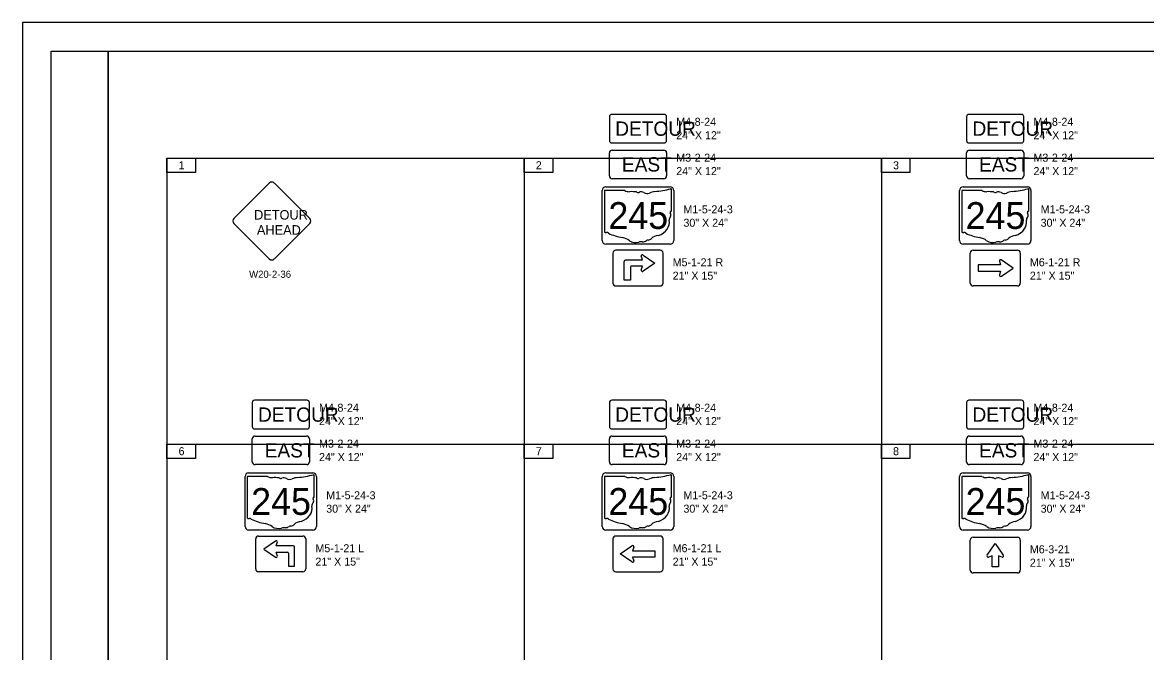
# Model space of a CAD drawing. Extents: x 0 to 718, y 0 to 440.
# Drawn here: x 0 to 393, y 220 to 440 of the extents above; entities that cross this region are included whole.
import ezdxf

# ---------------------------------------------------------------- set-up
doc = ezdxf.new("R2010")
doc.units = 0
for name, color, linetype in [('SC_Scratch1', 7, 'Continuous'), ('SH_Border', 7, 'Continuous'), ('SH_Cut_Line', 7, 'Continuous'), ('SH_Text', 7, 'Continuous'), ('SN_P_Signs', 7, 'Continuous'), ('SN_P_Text', 7, 'Continuous')]:
    doc.layers.add(name, color=color, linetype=linetype)

msp = doc.modelspace()

# ---------------------------------------------------------------- linework, layer by layer
at = {"layer": 'SC_Scratch1'}
for p, q in [((50.54, 392.53), (50.54, 292.53)), ((50.54, 392.53), (225.54, 392.53)), ((175.54, 392.53), (175.54, 292.53)), ((225.54, 392.53), (375.54, 392.53)), ((300.54, 392.53), (300.54, 292.53)), ((375.54, 392.53), (550.54, 392.53)), ((50.54, 292.53), (50.54, 192.53)), ((50.54, 292.53), (225.54, 292.53)), ((175.54, 292.53), (175.54, 192.53)), ((225.54, 292.53), (375.54, 292.53)), ((300.54, 292.53), (300.54, 192.53)), ((375.54, 292.53), (550.54, 292.53))]:
    msp.add_line(p, q, dxfattribs=at)
at = {"layer": 'SH_Border'}
for points in [[(10, 430), (30, 430), (30, 10), (10, 10)], [(30, 430), (670, 430), (670, 10), (30, 10)]]:
    msp.add_lwpolyline(points, close=True, dxfattribs=at)
at = {"layer": 'SH_Cut_Line'}
msp.add_lwpolyline([(0, 0), (680, 0), (680, 440), (0, 440)], close=True, dxfattribs=at)
at = {"layer": 'SH_Text'}
for points in [[(50.54, 392.53), (60.54, 392.53), (60.54, 387.53), (50.54, 387.53)], [(175.54, 392.53), (185.54, 392.53), (185.54, 387.53), (175.54, 387.53)], [(300.54, 392.53), (310.54, 392.53), (310.54, 387.53), (300.54, 387.53)], [(50.54, 292.53), (60.54, 292.53), (60.54, 287.53), (50.54, 287.53)], [(175.54, 292.53), (185.54, 292.53), (185.54, 287.53), (175.54, 287.53)], [(300.54, 292.53), (310.54, 292.53), (310.54, 287.53), (300.54, 287.53)]]:
    msp.add_lwpolyline(points, close=True, dxfattribs=at)
at = {"layer": 'SN_P_Signs'}
for p, q in [((205.39, 386.37), (205.39, 394.37)), ((206.39, 395.37), (224.39, 395.37)), ((225.39, 394.37), (225.39, 386.37)), ((330.39, 386.37), (330.39, 394.37)), ((331.39, 395.37), (349.39, 395.37)), ((350.39, 394.37), (350.39, 386.37)), ((224.39, 385.37), (206.39, 385.37)), ((349.39, 385.37), (331.39, 385.37)), ((210.76, 381.26), (203.9, 381.26)), ((227.11, 374.17), (227.11, 381.61)), ((335.76, 381.26), (328.9, 381.26)), ((352.11, 374.17), (352.11, 381.61)), ((203.67, 381.02), (203.67, 366.79)), ((328.67, 381.02), (328.67, 366.79)), ((227.1, 374.17), (227.11, 374.17)), ((352.1, 374.17), (352.11, 374.17)), ((206.64, 359.37), (206.64, 348.87)), ((223.14, 360.37), (207.64, 360.37)), ((216.95, 356.93), (216.53, 358.33)), ((217.24, 358.63), (221.32, 355.83)), ((224.14, 348.87), (224.14, 359.37)), ((331.64, 348.87), (331.64, 359.37)), ((332.64, 360.37), (348.14, 360.37)), ((349.14, 359.37), (349.14, 348.87)), ((210.54, 349.9), (210.54, 356.46)), ((211.01, 356.93), (216.95, 356.93)), ((211.01, 356.93), (211.01, 356.93)), ((212.73, 354.43), (212.73, 349.9)), ((216.95, 354.74), (213.04, 354.74)), ((216.53, 353.33), (216.95, 354.74)), ((221.32, 355.83), (217.24, 353.04)), ((342.26, 355.21), (334.45, 355.21)), ((334.45, 355.21), (334.45, 353.02)), ((341.86, 356.49), (342.26, 355.21)), ((346.64, 354.12), (342.5, 356.96)), ((342.56, 351.32), (346.64, 354.12)), ((212.73, 349.9), (210.54, 349.9)), ((334.45, 353.02), (342.26, 353.02)), ((342.26, 353.02), (341.86, 351.74)), ((207.64, 347.87), (223.14, 347.87)), ((348.14, 347.87), (332.64, 347.87)), ((81.39, 295.37), (99.39, 295.37)), ((206.39, 295.37), (224.39, 295.37)), ((331.39, 295.37), (349.39, 295.37)), ((80.39, 286.37), (80.39, 294.37)), ((100.39, 294.37), (100.39, 286.37)), ((205.39, 286.37), (205.39, 294.37)), ((225.39, 294.37), (225.39, 286.37)), ((330.39, 286.37), (330.39, 294.37)), ((350.39, 294.37), (350.39, 286.37)), ((99.39, 285.37), (81.39, 285.37)), ((224.39, 285.37), (206.39, 285.37)), ((349.39, 285.37), (331.39, 285.37)), ((78.67, 281.02), (78.67, 266.79)), ((85.76, 281.26), (78.9, 281.26)), ((102.11, 274.17), (102.11, 281.61)), ((203.67, 281.02), (203.67, 266.79)), ((210.76, 281.26), (203.9, 281.26)), ((227.11, 274.17), (227.11, 281.61)), ((328.67, 281.02), (328.67, 266.79)), ((335.76, 281.26), (328.9, 281.26)), ((352.11, 274.17), (352.11, 281.61)), ((102.1, 274.17), (102.11, 274.17)), ((227.1, 274.17), (227.11, 274.17)), ((352.1, 274.17), (352.11, 274.17)), ((82.64, 260.37), (98.14, 260.37)), ((223.14, 260.37), (207.64, 260.37)), ((223.14, 260.37), (223.14, 260.37)), ((332.64, 259.99), (348.14, 259.99)), ((81.64, 248.87), (81.64, 259.37)), ((88.53, 258.63), (84.45, 255.83)), ((84.45, 255.83), (88.53, 253.04)), ((88.83, 256.93), (89.24, 258.33)), ((94.76, 256.93), (88.83, 256.93)), ((94.76, 256.93), (94.76, 256.93)), ((95.23, 249.9), (95.23, 256.46)), ((99.14, 259.37), (99.14, 248.87)), ((206.64, 259.37), (206.64, 248.87)), ((209.14, 254.12), (213.28, 256.96)), ((213.91, 256.49), (213.51, 255.21)), ((224.14, 248.87), (224.14, 259.37)), ((331.64, 248.49), (331.64, 258.99)), ((337.54, 253.66), (340.39, 257.8)), ((340.39, 257.8), (343.18, 253.72)), ((349.14, 258.99), (349.14, 248.49)), ((89.24, 253.33), (88.83, 254.74)), ((88.83, 254.74), (92.73, 254.74)), ((93.04, 254.43), (93.04, 249.9)), ((213.22, 251.32), (209.14, 254.12)), ((213.51, 255.21), (221.32, 255.21)), ((221.32, 253.02), (213.51, 253.02)), ((213.51, 253.02), (213.91, 251.74)), ((221.32, 255.21), (221.32, 253.02)), ((339.29, 253.42), (338.01, 253.03)), ((339.29, 249.67), (339.29, 253.42)), ((342.76, 253.03), (341.48, 253.42)), ((341.48, 253.42), (341.48, 249.67)), ((98.14, 247.87), (82.64, 247.87)), ((93.04, 249.9), (95.23, 249.9)), ((93.04, 249.9), (95.23, 249.9)), ((207.64, 247.87), (223.14, 247.87)), ((341.48, 249.67), (339.29, 249.67)), ((348.14, 247.49), (332.64, 247.49))]:
    msp.add_line(p, q, dxfattribs=at)
for points in [[(205.39, 407.07), (205.39, 398.67)], [(224.59, 407.87), (206.19, 407.87)], [(225.39, 398.67), (225.39, 407.07)], [(330.39, 407.07), (330.39, 398.67)], [(349.59, 407.87), (331.19, 407.87)], [(350.39, 398.67), (350.39, 407.07)], [(206.19, 397.87), (224.59, 397.87)], [(331.19, 397.87), (349.59, 397.87)], [(73.99, 371.46), (86.37, 383.83)], [(88.14, 383.83), (100.51, 371.46)], [(202.89, 363.74), (202.89, 381.24)], [(204.14, 382.49), (226.64, 382.49)], [(227.89, 381.24), (227.89, 363.74)], [(327.89, 363.74), (327.89, 381.24)], [(329.14, 382.49), (351.64, 382.49)], [(352.89, 381.24), (352.89, 363.74)], [(86.37, 357.32), (73.99, 369.69)], [(100.51, 369.69), (88.14, 357.32)], [(226.64, 362.49), (204.14, 362.49)], [(351.64, 362.49), (329.14, 362.49)], [(80.39, 307.07), (80.39, 298.67)], [(99.59, 307.87), (81.19, 307.87)], [(100.39, 298.67), (100.39, 307.07)], [(205.39, 307.07), (205.39, 298.67)], [(224.59, 307.87), (206.19, 307.87)], [(225.39, 298.67), (225.39, 307.07)], [(330.39, 307.07), (330.39, 298.67)], [(349.59, 307.87), (331.19, 307.87)], [(350.39, 298.67), (350.39, 307.07)], [(81.19, 297.87), (99.59, 297.87)], [(206.19, 297.87), (224.59, 297.87)], [(331.19, 297.87), (349.59, 297.87)], [(77.89, 263.74), (77.89, 281.24)], [(79.14, 282.49), (101.64, 282.49)], [(102.89, 281.24), (102.89, 263.74)], [(202.89, 263.74), (202.89, 281.24)], [(204.14, 282.49), (226.64, 282.49)], [(227.89, 281.24), (227.89, 263.74)], [(327.89, 263.74), (327.89, 281.24)], [(329.14, 282.49), (351.64, 282.49)], [(352.89, 281.24), (352.89, 263.74)], [(101.64, 262.49), (79.14, 262.49)], [(226.64, 262.49), (204.14, 262.49)], [(351.64, 262.49), (329.14, 262.49)]]:
    msp.add_lwpolyline(points, dxfattribs=at)
for centre, radius, start, end in [((206.19, 407.07), 0.8, 90, 180), ((224.59, 407.07), 0.8, 0, 90), ((331.19, 407.07), 0.8, 90, 180), ((349.59, 407.07), 0.8, 0, 90), ((206.19, 398.67), 0.8, 180, 270), ((224.59, 398.67), 0.8, 270, 0), ((331.19, 398.67), 0.8, 180, 270), ((349.59, 398.67), 0.8, 270, 0), ((206.39, 394.36), 1, 90, 180), ((224.39, 394.36), 1, 0, 90), ((331.39, 394.36), 1, 90, 180), ((349.39, 394.36), 1, 0, 90), ((206.39, 386.36), 1, 180, 270), ((224.39, 386.36), 1, 270, 0), ((331.39, 386.36), 1, 180, 270), ((349.39, 386.36), 1, 270, 0), ((87.25, 382.95), 1.25, 45, 135), ((204.14, 381.24), 1.25, 90, 180), ((226.64, 381.24), 1.25, 0, 90), ((329.14, 381.24), 1.25, 90, 180), ((351.64, 381.24), 1.25, 0, 90), ((74.88, 370.57), 1.25, 135, 225), ((99.63, 370.57), 1.25, 315, 45), ((204.14, 363.74), 1.25, 180, 270), ((226.64, 363.74), 1.25, 270, 0), ((329.14, 363.74), 1.25, 180, 270), ((351.64, 363.74), 1.25, 270, 0), ((207.64, 359.36), 1, 90, 180), ((216.95, 358.33), 0.417, 45.0001, 179.9983), ((223.14, 359.36), 1, 0, 90), ((332.64, 359.37), 1, 90, 180), ((348.14, 359.37), 1, 0, 90), ((87.25, 358.2), 1.25, 225, 315), ((211.01, 356.46), 0.469, 90, 180), ((213.04, 354.43), 0.312, 90, 180), ((342.26, 356.62), 0.417, 55.4112, 197.2046), ((216.95, 353.33), 0.417, 179.9983, 314.9999), ((342.26, 351.62), 0.417, 162.7954, 315.0096), ((207.64, 348.86), 1, 180, 270), ((223.14, 348.86), 1, 270, 0), ((332.64, 348.87), 1, 180, 270), ((348.14, 348.87), 1, 270, 360), ((81.19, 307.07), 0.8, 90, 180), ((99.59, 307.07), 0.8, 0, 90), ((206.19, 307.07), 0.8, 90, 180), ((224.59, 307.07), 0.8, 0, 90), ((331.19, 307.07), 0.8, 90, 180), ((349.59, 307.07), 0.8, 0, 90), ((81.19, 298.67), 0.8, 180, 270), ((81.39, 294.36), 1, 90, 180), ((99.39, 294.36), 1, 0, 90), ((99.59, 298.67), 0.8, 270, 0), ((206.19, 298.67), 0.8, 180, 270), ((206.39, 294.36), 1, 90, 180), ((224.39, 294.36), 1, 0, 90), ((224.59, 298.67), 0.8, 270, 0), ((331.19, 298.67), 0.8, 180, 270), ((331.39, 294.36), 1, 90, 180), ((349.39, 294.36), 1, 0, 90), ((349.59, 298.67), 0.8, 270, 0), ((81.39, 286.36), 1, 180, 270), ((99.39, 286.36), 1, 270, 0), ((206.39, 286.36), 1, 180, 270), ((224.39, 286.36), 1, 270, 0), ((331.39, 286.36), 1, 180, 270), ((349.39, 286.36), 1, 270, 0), ((79.14, 281.24), 1.25, 90, 180), ((101.64, 281.24), 1.25, 0, 90), ((204.14, 281.24), 1.25, 90, 180), ((226.64, 281.24), 1.25, 0, 90), ((329.14, 281.24), 1.25, 90, 180), ((351.64, 281.24), 1.25, 0, 90), ((79.14, 263.74), 1.25, 180, 270), ((101.64, 263.74), 1.25, 270, 0), ((204.14, 263.74), 1.25, 180, 270), ((226.64, 263.74), 1.25, 270, 0), ((329.14, 263.74), 1.25, 180, 270), ((351.64, 263.74), 1.25, 270, 0), ((82.64, 259.37), 1, 90, 180), ((98.14, 259.37), 1, 0, 90), ((207.64, 259.37), 1, 90, 180), ((223.14, 259.37), 1, 0, 90), ((332.64, 258.99), 1, 90, 180), ((348.14, 258.99), 1, 0, 90), ((88.83, 258.33), 0.417, 0.0017, 134.9999), ((94.76, 256.46), 0.469, 0, 90), ((213.51, 256.62), 0.417, 342.7954, 124.5888), ((88.83, 253.33), 0.417, 225.0001, 0.0017), ((92.73, 254.43), 0.312, 0, 90), ((213.51, 251.62), 0.417, 224.9904, 17.2046), ((337.89, 253.43), 0.417, 145.4112, 287.2046), ((342.89, 253.43), 0.417, 252.7954, 45.0096), ((82.64, 248.87), 1, 180, 270), ((98.14, 248.87), 1, 270, 360), ((207.64, 248.87), 1, 180, 270), ((223.14, 248.87), 1, 270, 0), ((332.64, 248.49), 1, 180, 270), ((348.14, 248.49), 1, 270, 0)]:
    msp.add_arc(centre, radius, start, end, dxfattribs=at)
for centre, major_axis, start_param, end_param in [((203.94, 381.05), (0.272, 0), 1.712693, 3.28349), ((212.4, 382.91), (2.63, 0), 4.042523, 4.731795), ((218.76, 400.66), (24.85, 0), 4.814394, 5.042369), ((226.85, 381.64), (0.261, 0), 6.141152, 7.989035), ((328.94, 381.05), (0.272, 0), 1.712693, 3.28349), ((337.4, 382.91), (2.63, 0), 4.042523, 4.731795), ((343.76, 400.66), (24.85, 0), 4.814394, 5.042369), ((351.85, 381.64), (0.261, 0), 6.141152, 7.989035), ((213.27, 373.27), (9.45, 0), 1.404758, 1.657858), ((215.42, 381.12), (0.76, 0), 3.836095, 5.185415), ((216.53, 379.48), (1.58, 0), 0.950623, 2.079405), ((218.57, 381.73), (1.9, 0), 4.081561, 5.145723), ((221.93, 376.91), (5, 0), 1.699011, 2.107814), ((338.27, 373.27), (9.45, 0), 1.404758, 1.657858), ((340.42, 381.12), (0.76, 0), 3.836095, 5.185415), ((341.53, 379.48), (1.58, 0), 0.950623, 2.079405), ((343.57, 381.73), (1.9, 0), 4.081561, 5.145723), ((346.93, 376.91), (5, 0), 1.699011, 2.107814), ((227.05, 373.62), (0.404, 0), 1.883978, 3.671073), ((224.48, 372.68), (2.42, 0), 5.934695, 6.695948), ((226.83, 374.14), (0.279, 0), 5.05454, 6.418171), ((352.05, 373.62), (0.404, 0), 1.883978, 3.671073), ((349.48, 372.68), (2.42, 0), 5.934695, 6.695948), ((351.83, 374.14), (0.279, 0), 5.05454, 6.418171), ((220.15, 370.11), (6.22, 0), 5.101752, 6.440018), ((228.04, 371.05), (1.76, 0), 2.387724, 3.262537), ((345.15, 370.11), (6.22, 0), 5.101752, 6.440018), ((353.04, 371.05), (1.76, 0), 2.387724, 3.262537), ((203.94, 366.75), (0.274, 0), 3.00124, 4.508301), ((203.98, 368.21), (2.09, 0), 4.665946, 4.897461), ((204.41, 365.96), (0.754, 0), 0.519207, 1.627899), ((213.93, 378.75), (17.95, 0), 4.195997, 4.488961), ((222.77, 362.79), (3.4, 0), 1.647645, 2.488434), ((328.94, 366.75), (0.274, 0), 3.00124, 4.508301), ((328.98, 368.21), (2.09, 0), 4.665946, 4.897461), ((329.41, 365.96), (0.754, 0), 0.519207, 1.627899), ((338.93, 378.75), (17.95, 0), 4.195997, 4.488961), ((347.77, 362.79), (3.4, 0), 1.647645, 2.488434), ((208.57, 360.39), (5.62, 0), 0.823519, 1.323587), ((214.65, 365.89), (3.56, 0), 4.026481, 4.996735), ((216.71, 360.97), (2.93, 0), 1.495662, 1.94098), ((216.97, 364.83), (1.9, 0), 4.691044, 5.507374), ((218.69, 363.45), (0.535, 0), 1.147584, 2.315152), ((218.46, 365.41), (2.01, 0), 4.937069, 5.64225), ((333.57, 360.39), (5.62, 0), 0.823519, 1.323587), ((339.65, 365.89), (3.56, 0), 4.026481, 4.996735), ((341.71, 360.97), (2.93, 0), 1.495662, 1.94098), ((341.97, 364.83), (1.9, 0), 4.691044, 5.507374), ((343.69, 363.45), (0.535, 0), 1.147584, 2.315152), ((343.46, 365.41), (2.01, 0), 4.937069, 5.64225), ((78.94, 281.05), (0.272, 0), 1.712693, 3.28349), ((87.4, 282.91), (2.63, 0), 4.042523, 4.731795), ((88.27, 273.27), (9.45, 0), 1.404758, 1.657858), ((90.42, 281.12), (0.76, 0), 3.836095, 5.185415), ((91.53, 279.48), (1.58, 0), 0.950623, 2.079405), ((93.57, 281.73), (1.9, 0), 4.081561, 5.145723), ((96.93, 276.91), (5, 0), 1.699011, 2.107814), ((93.76, 300.66), (24.85, 0), 4.814394, 5.042369), ((101.85, 281.64), (0.261, 0), 6.141152, 7.989035), ((203.94, 281.05), (0.272, 0), 1.712693, 3.28349), ((212.4, 282.91), (2.63, 0), 4.042523, 4.731795), ((213.27, 273.27), (9.45, 0), 1.404758, 1.657858), ((215.42, 281.12), (0.76, 0), 3.836095, 5.185415), ((216.53, 279.48), (1.58, 0), 0.950623, 2.079405), ((218.57, 281.73), (1.9, 0), 4.081561, 5.145723), ((221.93, 276.91), (5, 0), 1.699011, 2.107814), ((218.76, 300.66), (24.85, 0), 4.814394, 5.042369), ((226.85, 281.64), (0.261, 0), 6.141152, 7.989035), ((328.94, 281.05), (0.272, 0), 1.712693, 3.28349), ((337.4, 282.91), (2.63, 0), 4.042523, 4.731795), ((338.27, 273.27), (9.45, 0), 1.404758, 1.657858), ((340.42, 281.12), (0.76, 0), 3.836095, 5.185415), ((341.53, 279.48), (1.58, 0), 0.950623, 2.079405), ((343.57, 281.73), (1.9, 0), 4.081561, 5.145723), ((346.93, 276.91), (5, 0), 1.699011, 2.107814), ((343.76, 300.66), (24.85, 0), 4.814394, 5.042369), ((351.85, 281.64), (0.261, 0), 6.141152, 7.989035), ((103.04, 271.05), (1.76, 0), 2.387724, 3.262537), ((102.05, 273.62), (0.404, 0), 1.883978, 3.671073), ((99.48, 272.68), (2.42, 0), 5.934695, 6.695948), ((101.83, 274.14), (0.279, 0), 5.05454, 6.418171), ((228.04, 271.05), (1.76, 0), 2.387724, 3.262537), ((227.05, 273.62), (0.404, 0), 1.883978, 3.671073), ((224.48, 272.68), (2.42, 0), 5.934695, 6.695948), ((226.83, 274.14), (0.279, 0), 5.05454, 6.418171), ((353.04, 271.05), (1.76, 0), 2.387724, 3.262537), ((352.05, 273.62), (0.404, 0), 1.883978, 3.671073), ((349.48, 272.68), (2.42, 0), 5.934695, 6.695948), ((351.83, 274.14), (0.279, 0), 5.05454, 6.418171), ((95.15, 270.11), (6.22, 0), 5.101752, 6.440018), ((220.15, 270.11), (6.22, 0), 5.101752, 6.440018), ((345.15, 270.11), (6.22, 0), 5.101752, 6.440018), ((78.94, 266.75), (0.274, 0), 3.00124, 4.508301), ((78.98, 268.21), (2.09, 0), 4.665946, 4.897461), ((79.41, 265.96), (0.754, 0), 0.519207, 1.627899), ((88.93, 278.75), (17.95, 0), 4.195997, 4.488961), ((83.57, 260.39), (5.62, 0), 0.823519, 1.323587), ((89.65, 265.89), (3.56, 0), 4.026481, 4.996735), ((91.71, 260.97), (2.93, 0), 1.495662, 1.94098), ((91.97, 264.83), (1.9, 0), 4.691044, 5.507374), ((93.69, 263.45), (0.535, 0), 1.147584, 2.315152), ((93.46, 265.41), (2.01, 0), 4.937069, 5.64225), ((97.77, 262.79), (3.4, 0), 1.647645, 2.488434), ((203.94, 266.75), (0.274, 0), 3.00124, 4.508301), ((203.98, 268.21), (2.09, 0), 4.665946, 4.897461), ((204.41, 265.96), (0.754, 0), 0.519207, 1.627899), ((213.93, 278.75), (17.95, 0), 4.195997, 4.488961), ((208.57, 260.39), (5.62, 0), 0.823519, 1.323587), ((214.65, 265.89), (3.56, 0), 4.026481, 4.996735), ((216.71, 260.97), (2.93, 0), 1.495662, 1.94098), ((216.97, 264.83), (1.9, 0), 4.691044, 5.507374), ((218.69, 263.45), (0.535, 0), 1.147584, 2.315152), ((218.46, 265.41), (2.01, 0), 4.937069, 5.64225), ((222.77, 262.79), (3.4, 0), 1.647645, 2.488434), ((328.94, 266.75), (0.274, 0), 3.00124, 4.508301), ((328.98, 268.21), (2.09, 0), 4.665946, 4.897461), ((329.41, 265.96), (0.754, 0), 0.519207, 1.627899), ((338.93, 278.75), (17.95, 0), 4.195997, 4.488961), ((333.57, 260.39), (5.62, 0), 0.823519, 1.323587), ((339.65, 265.89), (3.56, 0), 4.026481, 4.996735), ((341.71, 260.97), (2.93, 0), 1.495662, 1.94098), ((341.97, 264.83), (1.9, 0), 4.691044, 5.507374), ((343.69, 263.45), (0.535, 0), 1.147584, 2.315152), ((343.46, 265.41), (2.01, 0), 4.937069, 5.64225), ((347.77, 262.79), (3.4, 0), 1.647645, 2.488434)]:
    msp.add_ellipse(centre, major_axis=major_axis, ratio=0.8, start_param=start_param, end_param=end_param, dxfattribs=at)

# ---------------------------------------------------------------- texts
at = {"layer": 'SH_Text'}
for s, p in [('1', (54.63, 388.66)), ('2', (179.63, 388.66)), ('3', (304.63, 388.66)), ('6', (54.63, 288.66)), ('7', (179.63, 288.66)), ('8', (304.63, 288.66))]:
    msp.add_text(s, height=2.8, dxfattribs=at).set_placement(p)
at = {"layer": 'SN_P_Signs'}
for s, height, p in [('DETOUR', 5, (207.42, 400.37)), ('DETOUR', 5, (332.42, 400.37)), ('EAST', 5, (209.75, 387.87)), ('EAST', 5, (334.75, 387.87)), ('245', 9.375, (205.03, 367.79)), ('245', 9.375, (330.03, 367.79)), ('DETOUR', 3.333, (81.05, 371.06)), ('AHEAD', 3.333, (82.05, 365.78)), ('DETOUR', 5, (82.42, 300.37)), ('DETOUR', 5, (207.42, 300.37)), ('DETOUR', 5, (332.42, 300.37)), ('EAST', 5, (84.75, 287.87)), ('EAST', 5, (209.75, 287.87)), ('EAST', 5, (334.75, 287.87)), ('245', 9.375, (80.03, 267.79)), ('245', 9.375, (205.03, 267.79)), ('245', 9.375, (330.03, 267.79))]:
    msp.add_text(s, height=height, dxfattribs=at).set_placement(p)
at = {"layer": 'SN_P_Text'}
for s, height, p in [('M4-8-24', 2.8, (228.77, 403.87)), ('M4-8-24', 2.8, (353.77, 403.87)), ('24" X 12"', 2.8, (228.77, 399.18)), ('24" X 12"', 2.8, (353.77, 399.18)), ('M3-2-24', 2.8, (228.77, 391.31)), ('M3-2-24', 2.8, (353.77, 391.31)), ('24" X 12"', 2.8, (228.77, 386.62)), ('24" X 12"', 2.8, (353.77, 386.62)), ('M1-5-24-3', 2.8, (231.28, 373.25)), ('M1-5-24-3', 2.8, (356.28, 373.25)), ('30" X 24"', 2.8, (231.28, 368.56)), ('30" X 24"', 2.8, (356.28, 368.56)), ('M5-1-21 R', 2.8, (227.51, 354.73)), ('M6-1-21 R', 2.8, (352.51, 354.73)), ('W20-2-36', 2.5, (79.3, 350.7)), ('21" X 15"', 2.8, (227.51, 350.04)), ('21" X 15"', 2.8, (352.51, 350.04)), ('M4-8-24', 2.8, (103.77, 303.87)), ('M4-8-24', 2.8, (228.77, 303.87)), ('M4-8-24', 2.8, (353.77, 303.87)), ('24" X 12"', 2.8, (103.77, 299.18)), ('24" X 12"', 2.8, (228.77, 299.18)), ('24" X 12"', 2.8, (353.77, 299.18)), ('M3-2-24', 2.8, (103.77, 291.31)), ('M3-2-24', 2.8, (228.77, 291.31)), ('M3-2-24', 2.8, (353.77, 291.31)), ('24" X 12"', 2.8, (103.77, 286.62)), ('24" X 12"', 2.8, (228.77, 286.62)), ('24" X 12"', 2.8, (353.77, 286.62)), ('M1-5-24-3', 2.8, (106.28, 273.25)), ('M1-5-24-3', 2.8, (231.28, 273.25)), ('M1-5-24-3', 2.8, (356.28, 273.25)), ('30" X 24"', 2.8, (106.28, 268.56)), ('30" X 24"', 2.8, (231.28, 268.56)), ('30" X 24"', 2.8, (356.28, 268.56)), ('M5-1-21 L', 2.8, (102.51, 254.73)), ('M6-1-21 L', 2.8, (227.51, 254.73)), ('M6-3-21', 2.8, (352.51, 254.35)), ('21" X 15"', 2.8, (102.51, 250.04)), ('21" X 15"', 2.8, (227.51, 250.04)), ('21" X 15"', 2.8, (352.51, 249.66))]:
    msp.add_text(s, height=height, dxfattribs=at).set_placement(p)

doc.saveas('drawing.dxf')
